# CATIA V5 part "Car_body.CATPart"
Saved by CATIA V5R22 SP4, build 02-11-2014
Part number: Car_body
Bounding box of the stored display mesh (mm): x -1630 to 291.243, y -652.567 to 652.567, z -165.044 to 580
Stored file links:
  C:\DATA\Car_ASSY\教育モデル\5_ASM\FIN\Car_body.CATPart
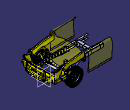
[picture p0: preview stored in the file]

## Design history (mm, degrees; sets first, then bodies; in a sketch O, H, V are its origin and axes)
Body1 (main body)
Body2 "Shass"
  Solid1: solid without history
  Translate1: ToTransfor Solid1, Direction (1, 0, 0), Length -5
Body3 "Body"
  Solid2: solid without history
